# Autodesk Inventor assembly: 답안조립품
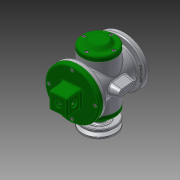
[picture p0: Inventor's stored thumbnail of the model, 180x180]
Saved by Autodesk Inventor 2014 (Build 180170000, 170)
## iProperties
Created: 2018-02
Part Number: 답안조립품
Document SubType Name: Assembly
Designer: kb542
Author: kb542
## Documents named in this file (18)
- C:\Users\kb542\Desktop\480207v1017\답안조립품.iam
- C:\Users\kb542\Desktop\480207v1017\본체.ipt
- C:\Users\kb542\Desktop\480207v1017\E-링.ipt
- C:\Users\kb542\Desktop\480207v1017\V-벨트풀리.ipt
- C:\Users\kb542\Desktop\480207v1017\덮개.ipt
- C:\Users\kb542\Desktop\480207v1017\뒤커버.ipt
- C:\Users\kb542\Desktop\480207v1017\링크.ipt
- C:\Users\kb542\Desktop\480207v1017\베어링 17 x 40 x 12.ipt
- C:\Users\kb542\Desktop\480207v1017\볼트 M4 x 8.ipt
- C:\Users\kb542\Desktop\480207v1017\볼트 M4 x 10.ipt
- C:\Users\kb542\Desktop\480207v1017\슬라이더.ipt
- C:\Users\kb542\Desktop\480207v1017\앞커버.ipt
- C:\Users\kb542\Desktop\480207v1017\오일 실 17 30 8.ipt
- C:\Users\kb542\Desktop\480207v1017\와셔 4x16.ipt
- C:\Users\kb542\Desktop\480207v1017\클레비스 핀 6 x 22.ipt
- 클레비스 핀 6 x 22.ipt
- C:\Users\kb542\Desktop\480207v1017\키 4 x 4 x 12.ipt
- C:\Users\kb542\Desktop\480207v1017\편심축.ipt
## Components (2 placed, 2 different names)
1. V-벨트풀리:1
2. E-링:1
